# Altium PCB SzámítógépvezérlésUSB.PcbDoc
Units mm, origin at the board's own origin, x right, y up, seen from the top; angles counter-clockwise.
Board outline 152.4 x 101.6 mm, 2 copper layers (Top Layer, Bottom Layer); 19 components, 15 nets, 67 pads, 0 vias.
Unrouted connection lines stored in the file: 2.
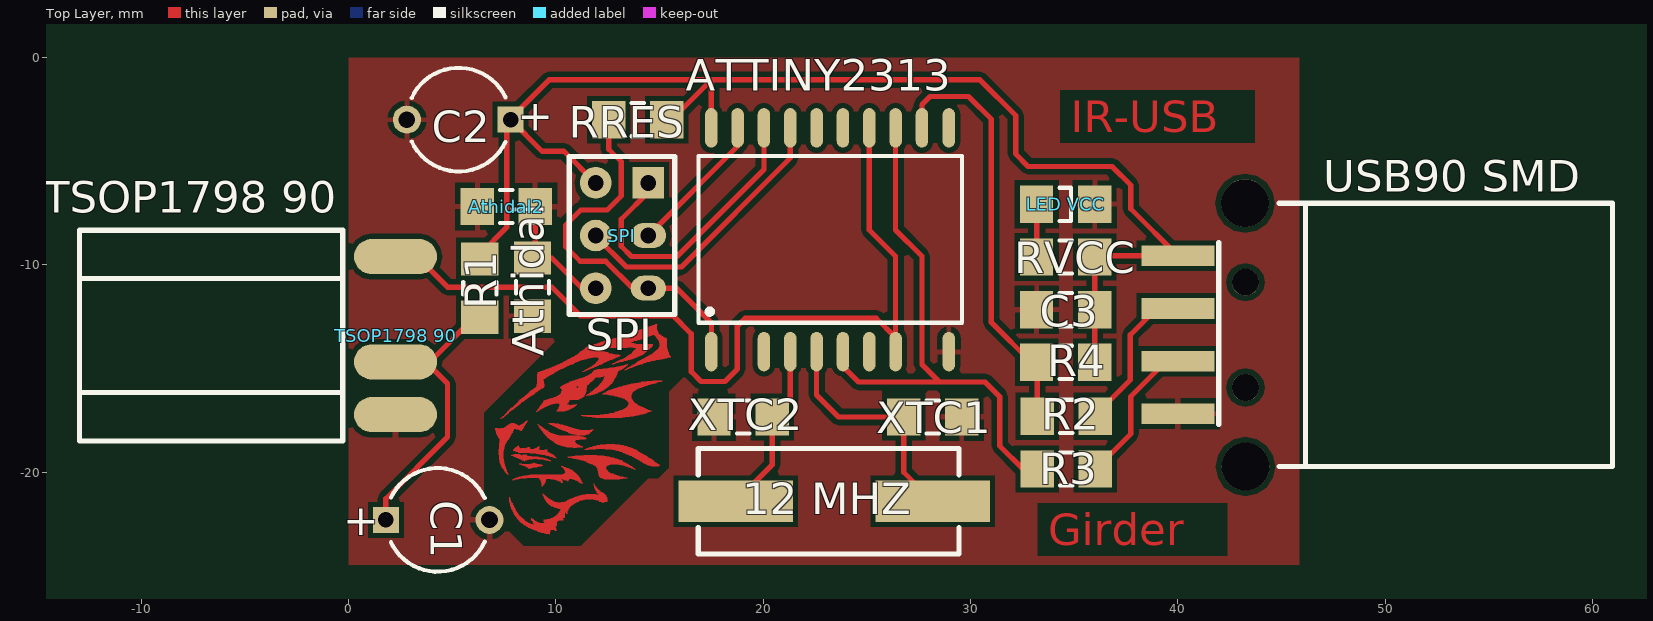
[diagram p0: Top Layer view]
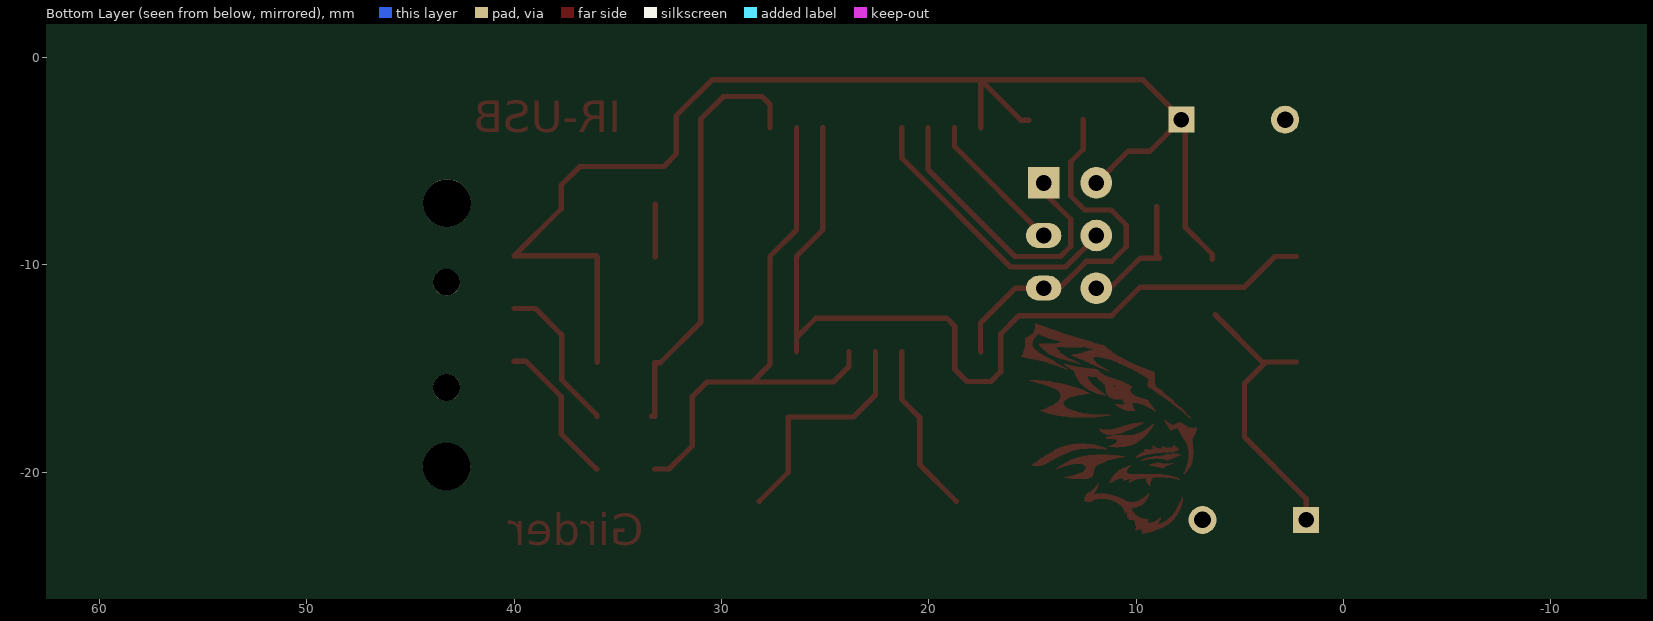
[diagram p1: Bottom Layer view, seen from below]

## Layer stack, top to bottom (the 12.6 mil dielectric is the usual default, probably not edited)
Top Layer: signal copper 0.0356
Dielectric: dielectric 0.32, FR-4, Dk 4.8
Bottom Layer: signal copper 0.036

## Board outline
-45.995,-61.098 106.405,-61.098 106.405,40.502 -45.995,40.502

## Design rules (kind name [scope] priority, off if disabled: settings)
Clearance [All] p1: gap=0.254
ComponentClearance [All] p1: gap=0.254 collisioncheckmode=3 verticalgap=0.254
PolygonConnect [All] p1: connectstyle=Relief reliefconductorwidth=0.254 reliefentries=4 polygonreliefangle="90 Angle"
RoutingVias [All] p1: holewidth=0.711 width=1.27 viastyle="Through Hole" minholewidth=0.711 minwidth=1.27 maxholewidth=0.711 maxwidth=1.27
SolderMaskExpansion [All] p1: expansion=0.102
TestPointUsage [All] p1: valid=0 allowmultiple=FALSE
Testpoint [All] p1: side=15 testpointundercomponent=TRUE minsize=1.016 maxsize=2.54 preferedsize=1.524 minholesize=0 maxholesize=1.016 preferedholesize=0.813 testpointgrid=0.025 style=1023 order=0123456789
Width [All] p1: maxlimit=0.254 minlimit=0.254 preferedwidth=0.254
18 further rules are at their usual default settings.

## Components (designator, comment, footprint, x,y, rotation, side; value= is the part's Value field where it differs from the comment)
"12 MHZ" "12 MHZ" Quartz 28.173,-21.401 r180 top (schematic designator "? MHZ")
Athidal "Res" "SM 3216[1206]" 8.869,-11.075 r90 top
Athidal2 "Res" "SM 3216[1206]" 7.602,-7.187 r180 top
ATTINY2313 "ATTINY2313" ATTINY2313 17.505,-14.172 r0 top
C1 "Cap Pol1" CAPPR5-5x5 4.297,-22.3 r0 top
C2 "Cap Pol1" CAPPR5-5x5 5.313,-2.996 r180 top
C3 "Cap" "SM 3216[1206]" 34.585,-12.158 r180 top
"LED VCC" "LED" "SM 3216[1206] - pol" 34.585,-7.078 r0 top
R1 "Res" "SM 3216[1206]" 6.329,-11.124 r90 top
R2 "Res" "SM 3216[1206]" 34.61,-17.303 r0 top
R3 "Res" "SM 3216[1206]" 34.61,-19.843 r0 top
R4 "Res" "SM 3216[1206]" 34.585,-14.698 r180 top
RRES "Res" "SM 3216[1206]" 13.949,-2.996 r180 top
RVCC "Res" "SM 3216[1206]" 34.585,-9.618 r180 top
SPI "SPI" SPI 11.917,-6.044 r0 top
"TSOP1798 90" "TSOP17xx90°" TSOP17xx90° 2.265,-17.22 r0 top (schematic designator TSOP17xx90°)
"USB90 SMD" "USB90° SMD" "USB90° SMD" 46.155,-7.025 r270 top (schematic designator "USB90° SMD")
XTC1 "Cap" "SM 3216[1206]" 28.173,-17.337 r0 top
XTC2 "Cap" "SM 3216[1206]" 19.029,-17.337 r180 top

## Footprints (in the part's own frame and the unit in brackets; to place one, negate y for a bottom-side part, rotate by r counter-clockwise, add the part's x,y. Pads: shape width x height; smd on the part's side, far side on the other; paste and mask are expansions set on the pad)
ATTINY2313 [mm]
  oval 0.6x1.9 smd: 1(-0.013,-0.013) 3(2.527,-0.013) 4(3.797,-0.013) 5(5.067,-0.013) 6(6.337,-0.013) 7(7.607,-0.013) 8(8.877,-0.013) 10(11.443,-0.013) 11(11.443,10.782) 12(10.147,10.782) 13(8.877,10.782) 14(7.607,10.782) 15(6.337,10.782) 16(5.067,10.782) 17(3.797,10.782) 18(2.527,10.782) 19(1.257,10.782) 20(-0.013,10.782)
  round 0 smd: 2(1.257,-0.013) 9(10.147,-0.013)
  silkscreen extent -0.62,1.38 12.08,9.42
CAPPR5-5x5 [mm] "Capacitor, Electrolytic, Radial; Body 5 x 5 mm (Dia.xH typ); Pin Spacing 5 mm (typ)"
  rect 1.25x1.25 hole 0.75: 1(-2.5,0)
  round 1.35 hole 0.8: 2(2.5,0)
  silkscreen extent -2.26,-2.5 2.27,2.5
Quartz [mm]
  rect 5.5x2 smd: 1(0,0) 2(9.5,0)
  silkscreen extent -1.27,-2.54 11.3,2.54
"SM 3216[1206]" [mm] "Chip Resistor; Body 3.2 x 1.6 mm (LxW typ)"
  rect 1.6x1.8 smd: 1(-1.4,0) 2(1.4,0)
  silkscreen extent -0.3,-0.8 0.3,0.8
"SM 3216[1206] - pol" [mm] "Polarized Chip; Body 3.2 x 1.6 mm (LxW typ)"
  rect 1.6x1.8 smd: 1(-1.4,0) 2(1.4,0)
  silkscreen extent -0.3,-0.8 0.25,0.8
SPI [mil]
  round 60 hole 30: 1(0,0) 3(0,-100) 5(0,-200)
  rect 60x60 hole 30: 2(100,0)
  oval 66.93x47.24 hole 30: 4(100,-100) 6(100,-200)
  silkscreen extent -50,-250 150,50
TSOP17xx90° [mm]
  oval 4x1.7 smd: 1(0,0) 2(0,2.54) 3(0,7.62)
  silkscreen extent -15.24,-1.27 -2.54,8.89
"USB90° SMD" [mm]
  round 2.3 hole 2.3: 0(0,-2.921) 0(12.7,-2.9)
  round 1.3 hole 1.3: 0(3.81,-2.9) 0(8.89,-2.9)
  rect 1x3.5 smd: 1(2.54,-6.155) 2(5.08,-6.155) 3(7.62,-6.155) 4(10.16,-6.155)
  silkscreen extent 0,-4.19 12.7,14.8

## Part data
"12 MHZ": library part Quartz, "SMD"
Athidal Athidal2 R1 R2 R3 R4 RRES RVCC: "Resistor"
C1 C2: "Polarized Capacitor (Radial)"
C3 XTC1 XTC2: "Capacitor"

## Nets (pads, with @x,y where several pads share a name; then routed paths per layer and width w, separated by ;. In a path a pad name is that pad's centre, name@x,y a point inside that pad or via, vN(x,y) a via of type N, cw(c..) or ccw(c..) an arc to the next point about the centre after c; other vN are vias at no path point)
GND: "LED VCC.2" "TSOP1798 90.1" "USB90 SMD.4" Athidal2.1 Athidal2.2 Athidal.1 Athidal.2 ATTINY2313.10 C1.2 C2.2 C3.2 SPI.5 XTC1.2 XTC2.2 | length 6.2
  Top Layer w0.254: Athidal.2 9.8,-9.675 11.249,-11.124 SPI.5 ; Athidal.2 9.002,-9.542 Athidal2.1
MISO: ATTINY2313.18 SPI.2 | length 14.4
  Top Layer w0.254: SPI.2 14.457,-6.493 13.15,-7.8 13.15,-9.1 13.642,-9.592 15.833,-9.592 20.032,-5.393 ATTINY2313.18
MOSI: ATTINY2313.17 SPI.3 | length 13.7
  Top Layer w0.254: SPI.3 11.917,-8.617 13.4,-10.1 16.05,-10.1 21.302,-4.848 ATTINY2313.17
NetC1_1: "TSOP1798 90.2" C1.1 R1.1 | length 14
  Top Layer w0.254: C1.1 1.797,-21.278 4.775,-18.3 4.775,-15.725 3.73,-14.68 2.265,-14.68 ; 3.913,-14.68 R1.1@6.199,-12.394
"NetLED VCC_1": "LED VCC.1" RVCC.2 | length 2.5
  Top Layer w0.254: RVCC.2 33.185,-7.078
NetR2_2: "USB90 SMD.2" R2.2 | length 7.5
  Top Layer w0.254: R2.2 36.01,-17.24 37.7,-15.55 37.7,-13.375 38.97,-12.105 40,-12.105
NetR3_2: "USB90 SMD.3" R3.2 | length 7.2
  Top Layer w0.254: R3.2 36.032,-19.843 37.725,-18.15 37.725,-16.35 39.43,-14.645 40,-14.645
PB0: ATTINY2313.12 R2.1 R4.2 | length 20.6
  Top Layer w0.254: ATTINY2313.12 27.652,-2.273 28.05,-1.875 29.9,-1.875 31,-2.975 31,-12.775 32.948,-14.723 33.21,-14.723 R2.1 R2.1@33.372,-17.303
PB1: ATTINY2313.6 ATTINY2313.13 R3.1 | length 26.7
  Top Layer w0.254: ATTINY2313.6 23.842,-14.892 24.6,-15.65 30.7,-15.65 31.4,-16.35 31.4,-18.725 32.518,-19.843 R3.1 ; ATTINY2313.13 26.382,-8.312 27.652,-9.582 27.652,-14.802 28.5,-15.65
PB2: "TSOP1798 90.3" ATTINY2313.8 ATTINY2313.14 | length 41.9
  Top Layer w0.254: 2.265,-9.6 3.3,-9.6 4.775,-11.075 9.8,-11.075 11.175,-12.45 15.65,-12.45 16.525,-13.325 16.525,-15.15 17,-15.625 18.15,-15.625 18.75,-15.025 18.75,-12.95 19.125,-12.575 25.45,-12.575 ATTINY2313.8@26.382,-13.507 ; ATTINY2313.14 25.112,-8.312 26.382,-9.582 ATTINY2313.8
RES: ATTINY2313.1 RRES.2 SPI.6 | length 18.2
  Top Layer w0.254: RRES.2 12.549,-4.424 13.15,-5.025 13.15,-6.675 12.475,-7.35 11.2,-7.35 10.475,-8.075 10.475,-9.125 11.175,-9.825 12.4,-9.825 13.699,-11.124 15.824,-11.124 17.5,-12.8 17.5,-14.177 ATTINY2313.1
SCK: ATTINY2313.19 SPI.4 | length 7
  Top Layer w0.254: SPI.4 18.762,-4.279 ATTINY2313.19
VCC: "USB90 SMD.1" ATTINY2313.20 C2.1 C3.1 R1.2 R4.1 RRES.1 RVCC.1 SPI.1 | length 65.5
  Top Layer w0.254: R1.2 6.329,-9.487 7.625,-8.191 7.625,-3.184 C2.1 9.337,-4.52 10.393,-4.52 SPI.1 ; C2.1@7.783,-2.966 9.675,-1.075 30.45,-1.075 32.175,-2.8 32.175,-4.65 32.775,-5.25 36.825,-5.25 37.725,-6.15 37.725,-7.29 40,-9.565 36.038,-9.565 RVCC.1 R4.1 ; RRES.1@15.174,-3.021 15.564,-3.021 17.492,-1.093 ATTINY2313.20
XT1: "12 MHZ.1" ATTINY2313.5 XTC1.1 | length 11.4
  Top Layer w0.254: ATTINY2313.5 22.572,-16.272 23.637,-17.337 XTC1.1 26.773,-20.001 28.173,-21.401
XT2: "12 MHZ.2" ATTINY2313.4 XTC2.1 | length 8.3
  Top Layer w0.254: 18.673,-21.401 20.429,-19.645 XTC2.1 20.463,-17.337 21.302,-16.498 ATTINY2313.4
pads on no net: "USB90 SMD.0" ATTINY2313.2 ATTINY2313.3 ATTINY2313.7 ATTINY2313.9 ATTINY2313.11 ATTINY2313.15 ATTINY2313.16
copper on no net: | length 678.6
  Top Layer w0.025: 7.068,-17.933 7.957,-17.933 ; 7.068,-17.908 7.957,-17.908 ; 7.068,-17.882 7.221,-17.882 ; 7.094,-18.009 7.906,-18.009 ; 7.094,-17.984 7.932,-17.984 ; 7.094,-17.959 7.957,-17.959 ; 7.119,-18.111 7.856,-18.111 ; 7.119,-18.086 7.881,-18.086 ; 7.119,-18.06 7.906,-18.06 ; 7.119,-18.035 7.906,-18.035 ; 7.144,-18.136 7.856,-18.136 ; 7.17,-18.213 7.805,-18.213 ; 7.17,-18.187 7.83,-18.187 ; 7.17,-18.162 7.856,-18.162 ; 7.195,-18.238 7.805,-18.238 ; 7.221,-18.314 7.754,-18.314 ; 7.221,-18.289 7.779,-18.289 ; 7.221,-18.263 7.805,-18.263 ; 7.246,-19.127 7.449,-19.127 ; 7.246,-19.102 7.449,-19.102 ; 7.246,-19.076 7.449,-19.076 ; 7.246,-19.051 7.449,-19.051 ; 7.246,-19.025 7.449,-19.025 ; 7.246,-19 7.449,-19 ; 7.246,-18.975 7.449,-18.975 ; 7.246,-18.949 7.449,-18.949 ; 7.246,-18.924 7.475,-18.924 ; 7.246,-18.898 7.475,-18.898 ; 7.271,-19.381 7.475,-19.381 ; 7.271,-19.356 7.449,-19.356 ; 7.271,-19.33 7.449,-19.33 ; 7.271,-19.305 7.449,-19.305 ; 7.271,-19.279 7.449,-19.279 ; 7.271,-19.254 7.449,-19.254 ; 7.271,-19.229 7.449,-19.229 ; 7.271,-19.203 7.449,-19.203 ; 7.271,-19.178 7.449,-19.178 ; 7.271,-19.152 7.449,-19.152 ; 7.271,-18.873 7.475,-18.873 ; 7.271,-18.848 7.5,-18.848 ; 7.271,-18.822 7.5,-18.822 ; 7.271,-18.797 7.5,-18.797 ; 7.271,-18.771 7.5,-18.771 ; 7.271,-18.746 7.5,-18.746 ; 7.271,-18.721 7.525,-18.721 ; 7.271,-18.695 7.525,-18.695 ; 7.271,-18.67 7.525,-18.67 ; 7.271,-18.644 7.525,-18.644 ; 7.271,-18.619 7.551,-18.619 ; 7.271,-18.594 7.576,-18.594 ; 7.271,-18.365 7.729,-18.365 ; 7.271,-18.34 7.754,-18.34 ; 7.297,-19.508 7.5,-19.508 ; 7.297,-19.483 7.5,-19.483 ; 7.297,-19.457 7.475,-19.457 ; 7.297,-19.432 7.475,-19.432 ; 7.297,-19.406 7.475,-19.406 ; 7.297,-18.568 7.576,-18.568 ; 7.297,-18.543 7.602,-18.543 ; 7.297,-18.517 7.627,-18.517 ; 7.297,-18.492 7.627,-18.492 ; 7.297,-18.467 7.652,-18.467 ; 7.297,-18.441 7.678,-18.441 ; 7.297,-18.416 7.703,-18.416 ; 7.297,-18.39 7.729,-18.39 ; 7.322,-19.559 7.5,-19.559 ; 7.322,-19.533 7.5,-19.533 ; 7.348,-19.635 7.525,-19.635 ; 7.348,-19.61 7.525,-19.61 ; 7.348,-19.584 7.5,-19.584 ; 7.348,-17.882 8.414,-17.882 ; 7.348,-17.4 7.373,-17.4 ; 7.373,-19.686 7.525,-19.686 ; 7.373,-19.66 7.525,-19.66 ; 7.373,-17.374 7.398,-17.374 ; 7.398,-19.737 7.551,-19.737 ; 7.398,-19.711 7.551,-19.711 ; 7.424,-19.787 7.576,-19.787 ; 7.424,-19.762 7.576,-19.762 ; 7.424,-17.349 7.449,-17.349 ; 7.424,-17.324 7.475,-17.324 ; 7.449,-19.813 7.576,-19.813 ; 7.449,-17.298 7.5,-17.298 ; 7.475,-19.864 7.602,-19.864 ; 7.475,-19.838 7.576,-19.838 ; 7.5,-19.914 7.627,-19.914 ; 7.5,-19.889 7.627,-19.889 ; 7.5,-17.857 8.414,-17.857 ; 7.5,-17.273 7.525,-17.273 ; 7.5,-17.247 7.551,-17.247 ; 7.525,-19.94 7.627,-19.94 ; 7.525,-17.832 8.414,-17.832 ; 7.525,-17.222 7.576,-17.222 ; 7.551,-19.965 7.627,-19.965 ; 7.551,-17.197 7.627,-17.197 ; 7.576,-19.991 7.652,-19.991 ; 7.576,-17.806 8.44,-17.806 ; 7.576,-17.171 7.652,-17.171 ; 7.602,-20.016 7.678,-20.016 ; 7.602,-17.781 8.44,-17.781 ; 7.602,-17.146 7.678,-17.146 ; 7.627,-20.041 7.678,-20.041 ; 7.627,-17.755 8.465,-17.755 ; 7.627,-17.12 7.729,-17.12 ; 7.652,-17.095 7.729,-17.095 ; 7.678,-20.092 7.703,-20.092 ; 7.678,-20.067 7.703,-20.067 ; 7.678,-17.73 8.186,-17.73 ; 7.678,-17.07 7.779,-17.07 ; 7.703,-17.705 8.135,-17.705 ; 7.729,-17.044 7.805,-17.044 ; 7.729,-17.019 7.83,-17.019 ; 7.754,-21.388 7.83,-21.388 ; 7.754,-21.362 7.83,-21.362 ; 7.754,-21.337 7.805,-21.337 ; 7.754,-21.311 7.805,-21.311 ; 7.754,-21.286 7.805,-21.286 ; 7.754,-21.261 7.805,-21.261 ; 7.754,-21.235 7.779,-21.235 ; 7.754,-21.21 7.779,-21.21 ; 7.754,-17.679 8.084,-17.679 ; 7.754,-16.993 7.881,-16.993 ; 7.779,-21.464 7.881,-21.464 ; 7.779,-21.438 7.856,-21.438 ; 7.779,-21.413 7.856,-21.413 ; 7.779,-17.654 8.033,-17.654 ; 7.779,-16.968 7.906,-16.968 ; 7.805,-21.616 7.957,-21.616 ; 7.805,-21.591 7.932,-21.591 ; 7.805,-21.565 7.906,-21.565 ; 7.805,-21.54 7.906,-21.54 ; 7.805,-21.515 7.906,-21.515 ; 7.805,-21.489 7.906,-21.489 ; 7.805,-16.943 7.957,-16.943 ; 7.83,-21.642 7.957,-21.642 ; 7.83,-16.917 7.957,-16.917 ; 7.856,-21.743 8.008,-21.743 ; 7.856,-21.718 7.983,-21.718 ; 7.856,-21.692 7.983,-21.692 ; 7.856,-21.667 7.983,-21.667 ; 7.856,-19.178 8.313,-19.178 ; 7.856,-17.628 7.983,-17.628 ; 7.856,-16.892 8.008,-16.892 ; 7.881,-21.794 8.033,-21.794 ; 7.881,-21.769 8.033,-21.769 ; 7.906,-21.87 8.084,-21.87 ; 7.906,-21.845 8.059,-21.845 ; 7.906,-21.819 8.059,-21.819 ; 7.906,-20.372 7.957,-20.372 ; 7.906,-20.346 8.008,-20.346 ; 7.906,-19.152 8.313,-19.152 ; 7.906,-16.866 8.033,-16.866 ; 7.932,-21.896 8.11,-21.896 ; 7.932,-19.203 8.618,-19.203 ; 7.932,-18.949 9.583,-18.949 ; 7.932,-18.924 9.227,-18.924 ; 7.932,-16.841 8.059,-16.841 ; 7.957,-21.972 8.16,-21.972 ; 7.957,-21.946 8.135,-21.946 ; 7.957,-21.921 8.135,-21.921 ; 7.957,-18.898 8.77,-18.898 ; 7.957,-16.816 8.11,-16.816 ; 7.983,-22.023 8.186,-22.023 ; 7.983,-21.997 8.186,-21.997 ; 7.983,-20.321 8.186,-20.321 ; 7.983,-19.229 8.821,-19.229 ; 7.983,-19.127 8.262,-19.127 ; 7.983,-18.873 8.77,-18.873 ; 7.983,-16.79 8.135,-16.79 ; 8.008,-22.048 8.211,-22.048 ; 8.008,-20.295 8.262,-20.295 ; 8.008,-18.848 8.262,-18.848 ; 8.008,-16.765 8.186,-16.765 ; 8.033,-22.099 8.262,-22.099 ; 8.033,-22.073 8.211,-22.073 ; 8.033,-18.975 9.583,-18.975 ; 8.033,-18.822 8.262,-18.822 ; 8.033,-16.739 8.186,-16.739 ; 8.059,-19.254 9.151,-19.254 ; 8.059,-16.714 8.237,-16.714 ; 8.084,-22.15 8.313,-22.15 ; 8.084,-22.124 8.287,-22.124 ; 8.084,-20.27 8.567,-20.27 ; 8.084,-19.279 9.227,-19.279 ; 8.084,-19 9.583,-19 ; 8.084,-18.797 8.237,-18.797 ; 8.084,-17.908 8.389,-17.908 ; 8.084,-16.689 8.262,-16.689 ; 8.11,-22.175 8.338,-22.175 ; 8.11,-18.771 8.211,-18.771 ; 8.135,-22.226 8.389,-22.226 ; 8.135,-22.2 8.364,-22.2 ; 8.135,-18.746 8.211,-18.746 ; 8.135,-16.663 8.313,-16.663 ; 8.135,-16.638 8.313,-16.638 ; 8.16,-22.251 8.414,-22.251 ; 8.186,-22.277 8.44,-22.277 ; 8.186,-20.245 11.132,-20.245 ; 8.186,-19.305 9.38,-19.305 ; 8.186,-19.025 9.634,-19.025 ; 8.186,-18.721 8.211,-18.721 ; 8.186,-16.612 8.364,-16.612 ; 8.211,-22.302 8.465,-22.302 ; 8.211,-19.33 9.456,-19.33 ; 8.211,-17.933 8.364,-17.933 ; 8.211,-16.587 8.414,-16.587 ; 8.211,-16.562 8.44,-16.562 ; 8.237,-22.327 8.491,-22.327 ; 8.237,-20.219 11.107,-20.219 ; 8.237,-19.584 8.364,-19.584 ; 8.262,-22.353 8.541,-22.353 ; 8.262,-17.959 8.364,-17.959 ; 8.262,-16.536 8.465,-16.536 ; 8.262,-16.511 8.491,-16.511 ; 8.287,-22.378 8.592,-22.378 ; 8.287,-19.356 8.872,-19.356 ; 8.287,-17.73 8.491,-17.73 ; 8.313,-19.61 9.227,-19.61 ; 8.313,-18.848 8.491,-18.848 ; 8.313,-17.984 8.364,-17.984 ; 8.313,-17.705 8.491,-17.705 ; 8.313,-16.485 8.541,-16.485 ; 8.338,-22.404 8.643,-22.404 ; 8.338,-16.46 8.567,-16.46 ; 8.364,-22.429 8.668,-22.429 ; 8.364,-20.194 11.107,-20.194 ; 8.364,-19.635 9.329,-19.635 ; 8.364,-19.406 8.592,-19.406 ; 8.364,-19.381 8.668,-19.381 ; 8.364,-19.178 8.592,-19.178 ; 8.364,-17.679 8.516,-17.679 ; 8.364,-16.435 8.618,-16.435 ; 8.389,-22.454 8.745,-22.454 ; 8.389,-17.654 8.541,-17.654 ; 8.389,-16.409 8.643,-16.409 ; 8.414,-22.48 8.795,-22.48 ; 8.414,-19.152 8.592,-19.152 ; 8.414,-16.384 8.668,-16.384 ; 8.44,-22.505 8.872,-22.505 ; 8.44,-20.168 11.081,-20.168 ; 8.44,-19.66 9.354,-19.66 ; 8.44,-19.432 8.491,-19.432 ; 8.44,-17.628 8.541,-17.628 ; 8.44,-17.603 8.567,-17.603 ; 8.465,-22.531 8.948,-22.531 ; 8.465,-19.457 8.491,-19.457 ; 8.465,-16.358 8.719,-16.358 ; 8.491,-19.686 9.303,-19.686 ; 8.491,-17.578 8.592,-17.578 ; 8.491,-16.333 8.745,-16.333 ; 8.516,-17.552 8.592,-17.552 ; 8.516,-16.308 8.795,-16.308 ; 8.541,-22.556 10.015,-22.556 ; 8.541,-18.848 8.745,-18.848 ; 8.541,-16.282 8.821,-16.282 ; 8.567,-19.711 9.151,-19.711 ; 8.592,-22.607 9.964,-22.607 ; 8.592,-22.581 9.938,-22.581 ; 8.592,-19.737 9.075,-19.737 ; 8.592,-18.822 8.745,-18.822 ; 8.592,-17.527 8.643,-17.527 ; 8.592,-16.257 8.872,-16.257 ; 8.592,-16.231 8.897,-16.231 ; 8.643,-20.143 11.056,-20.143 ; 8.643,-19.762 8.897,-19.762 ; 8.643,-18.797 8.745,-18.797 ; 8.643,-16.206 8.948,-16.206 ; 8.668,-22.658 9.964,-22.658 ; 8.668,-22.632 9.964,-22.632 ; 8.668,-19.787 8.821,-19.787 ; 8.668,-16.181 8.948,-16.181 ; 8.694,-16.155 8.999,-16.155 ; 8.719,-19.813 8.745,-19.813 ; 8.719,-16.13 9.049,-16.13 ; 8.77,-22.683 9.989,-22.683 ; 8.77,-20.118 11.031,-20.118 ; 8.77,-19.051 9.684,-19.051 ; 8.77,-16.104 9.1,-16.104 ; 8.795,-22.708 9.989,-22.708 ; 8.795,-19.584 9.075,-19.584 ; 8.795,-18.898 9.176,-18.898 ; 8.795,-16.079 9.126,-16.079 ; 8.821,-22.302 8.922,-22.302 ; 8.821,-22.277 8.897,-22.277 ; 8.821,-22.251 8.872,-22.251 ; 8.821,-22.226 8.846,-22.226 ; 8.821,-16.054 9.151,-16.054 ; 8.846,-22.327 8.973,-22.327 ; 8.872,-22.734 10.015,-22.734 ; 8.872,-22.378 9.075,-22.378 ; 8.872,-22.353 9.049,-22.353 ; 8.872,-16.028 9.202,-16.028 ; 8.872,-16.003 9.227,-16.003 ; 8.897,-22.759 10.015,-22.759 ; 8.897,-22.429 9.202,-22.429 ; 8.897,-22.404 9.151,-22.404 ; 8.897,-19.559 8.999,-19.559 ; 8.922,-22.454 10.04,-22.454 ; 8.922,-19.533 8.948,-19.533 ; 8.922,-15.977 9.278,-15.977 ; 8.948,-22.48 10.04,-22.48 ; 8.948,-18.873 9.176,-18.873 ; 8.948,-15.952 9.303,-15.952 ; 8.973,-22.785 9.735,-22.785 ; 8.973,-22.505 10.04,-22.505 ; 8.999,-22.531 10.04,-22.531 ; 8.999,-18.848 9.176,-18.848 ; 8.999,-15.927 9.354,-15.927 ; 9.024,-15.901 9.405,-15.901 ; 9.049,-19.076 9.735,-19.076 ; 9.049,-17.07 9.1,-17.07 ; 9.049,-15.876 9.405,-15.876 ; 9.075,-22.81 9.735,-22.81 ; 9.075,-18.822 9.202,-18.822 ; 9.075,-15.85 9.43,-15.85 ; 9.075,-15.825 9.43,-15.825 ; 9.075,-15.8 9.43,-15.8 ; 9.075,-15.774 9.43,-15.774 ; 9.075,-15.749 9.43,-15.749 ; 9.1,-18.797 9.202,-18.797 ; 9.1,-17.044 9.126,-17.044 ; 9.1,-17.019 9.151,-17.019 ; 9.1,-15.723 9.43,-15.723 ; 9.1,-15.698 9.405,-15.698 ; 9.1,-15.673 9.405,-15.673 ; 9.1,-15.647 9.405,-15.647 ; 9.1,-15.622 9.405,-15.622 ; 9.1,-15.596 9.38,-15.596 ; 9.1,-15.571 9.38,-15.571 ; 9.1,-15.546 9.38,-15.546 ; 9.1,-15.52 9.38,-15.52 ; 9.1,-15.495 9.405,-15.495 ; 9.1,-15.469 9.456,-15.469 ; 9.1,-15.444 9.507,-15.444 ; 9.1,-15.419 9.507,-15.419 ; 9.1,-15.393 9.583,-15.393 ; 9.1,-15.368 9.583,-15.368 ; 9.1,-15.342 9.659,-15.342 ; 9.1,-15.317 9.684,-15.317 ; 9.1,-15.292 9.735,-15.292 ; 9.1,-15.266 9.786,-15.266 ; 9.126,-22.835 9.735,-22.835 ; 9.126,-19.356 9.557,-19.356 ; 9.126,-17.679 9.151,-17.679 ; 9.126,-16.993 9.227,-16.993 ; 9.126,-16.968 9.227,-16.968 ; 9.126,-15.241 9.811,-15.241 ; 9.126,-15.215 9.888,-15.215 ; 9.126,-15.19 9.913,-15.19 ; 9.151,-18.771 9.202,-18.771 ; 9.151,-17.705 9.176,-17.705 ; 9.176,-20.27 11.158,-20.27 ; 9.176,-19.102 9.786,-19.102 ; 9.176,-18.746 9.202,-18.746 ; 9.176,-17.755 9.253,-17.755 ; 9.176,-17.73 9.202,-17.73 ; 9.176,-16.943 9.303,-16.943 ; 9.176,-16.917 9.329,-16.917 ; 9.202,-17.806 9.329,-17.806 ; 9.202,-17.781 9.278,-17.781 ; 9.202,-16.892 9.38,-16.892 ; 9.202,-16.866 9.405,-16.866 ; 9.227,-22.861 9.71,-22.861 ; 9.227,-20.321 9.532,-20.321 ; 9.227,-20.295 11.183,-20.295 ; 9.227,-17.857 9.354,-17.857 ; 9.227,-17.832 9.354,-17.832 ; 9.227,-16.841 9.456,-16.841 ; 9.227,-15.165 9.964,-15.165 ; 9.253,-20.346 9.507,-20.346 ; 9.253,-16.816 9.532,-16.816 ; 9.278,-20.422 9.507,-20.422 ; 9.278,-20.397 9.507,-20.397 ; 9.278,-20.372 9.507,-20.372 ; 9.278,-17.908 9.43,-17.908 ; 9.278,-17.882 9.405,-17.882 ; 9.278,-16.79 9.557,-16.79 ; 9.278,-16.765 9.634,-16.765 ; 9.278,-15.139 10.015,-15.139 ; 9.303,-22.886 9.71,-22.886 ; 9.303,-20.473 9.481,-20.473 ; 9.303,-20.448 9.481,-20.448 ; 9.303,-17.959 9.507,-17.959 ; 9.303,-17.933 9.481,-17.933 ; 9.303,-16.739 9.684,-16.739 ; 9.329,-20.651 9.354,-20.651 ; 9.329,-20.626 9.354,-20.626 ; 9.329,-20.6 9.38,-20.6 ; 9.329,-20.575 9.405,-20.575 ; 9.329,-20.549 9.43,-20.549 ; 9.329,-20.524 9.43,-20.524 ; 9.329,-20.499 9.456,-20.499 ; 9.329,-19.127 9.811,-19.127 ; 9.329,-17.984 9.557,-17.984 ; 9.329,-16.714 9.761,-16.714 ; 9.329,-16.689 9.811,-16.689 ; 9.354,-21.083 9.43,-21.083 ; 9.354,-21.057 9.38,-21.057 ; 9.354,-21.032 9.38,-21.032 ; 9.354,-18.035 9.634,-18.035 ; 9.354,-18.009 9.634,-18.009 ; 9.354,-16.663 9.938,-16.663 ; 9.354,-16.638 10.599,-16.638 ; 9.354,-15.114 10.065,-15.114 ; 9.38,-21.108 9.456,-21.108 ; 9.38,-18.06 9.71,-18.06 ; 9.38,-16.612 10.599,-16.612 ; 9.405,-22.353 10.065,-22.353 ; 9.405,-22.327 10.142,-22.327 ; 9.405,-22.302 10.345,-22.302 ; 9.405,-21.184 9.557,-21.184 ; 9.405,-21.159 9.507,-21.159 ; 9.405,-21.134 9.481,-21.134 ; 9.405,-19.381 9.634,-19.381 ; 9.405,-18.086 9.735,-18.086 ; 9.405,-16.587 10.624,-16.587 ; 9.405,-16.562 10.65,-16.562 ; 9.405,-15.088 10.091,-15.088 ; 9.43,-22.912 9.71,-22.912 ; 9.43,-22.378 10.04,-22.378 ; 9.43,-21.235 9.608,-21.235 ; 9.43,-21.21 9.583,-21.21 ; 9.43,-18.111 9.811,-18.111 ; 9.456,-22.429 10.04,-22.429 ; 9.456,-22.404 10.04,-22.404 ; 9.456,-21.286 9.684,-21.286 ; 9.456,-21.261 9.634,-21.261 ; 9.456,-18.924 9.583,-18.924 ; 9.456,-18.136 9.862,-18.136 ; 9.456,-16.536 10.65,-16.536 ; 9.481,-21.311 9.735,-21.311 ; 9.481,-19.406 9.659,-19.406 ; 9.481,-19.152 9.862,-19.152 ; 9.481,-18.162 9.964,-18.162 ; 9.481,-15.063 10.142,-15.063 ; 9.507,-22.937 9.71,-22.937 ; 9.507,-21.362 9.811,-21.362 ; 9.507,-21.337 9.761,-21.337 ; 9.507,-18.213 10.142,-18.213 ; 9.507,-18.187 10.015,-18.187 ; 9.532,-21.388 9.862,-21.388 ; 9.532,-16.511 10.65,-16.511 ; 9.532,-15.038 10.192,-15.038 ; 9.557,-21.413 9.938,-21.413 ; 9.557,-19.178 9.888,-19.178 ; 9.557,-18.263 11.183,-18.263 ; 9.557,-18.238 11.107,-18.238 ; 9.583,-22.277 10.345,-22.277 ; 9.583,-21.438 10.065,-21.438 ; 9.583,-18.289 11.31,-18.289 ; 9.608,-21.464 10.929,-21.464 ; 9.608,-18.314 11.361,-18.314 ; 9.608,-15.012 10.243,-15.012 ; 9.634,-21.489 10.878,-21.489 ; 9.634,-19.432 9.735,-19.432 ; 9.634,-16.485 11.081,-16.485 ; 9.659,-21.515 10.853,-21.515 ; 9.659,-18.34 11.437,-18.34 ; 9.659,-17.628 9.913,-17.628 ; 9.684,-22.962 9.71,-22.962 ; 9.684,-21.54 10.802,-21.54 ; 9.684,-19.203 9.913,-19.203 ; 9.684,-18.365 11.462,-18.365 ; 9.684,-16.46 11.132,-16.46 ; 9.684,-14.987 10.319,-14.987 ; 9.71,-19.457 9.761,-19.457 ; 9.71,-18.39 11.412,-18.39 ; 9.71,-17.654 10.142,-17.654 ; 9.735,-22.251 10.319,-22.251 ; 9.735,-21.565 10.777,-21.565 ; 9.735,-19.229 9.938,-19.229 ; 9.735,-18.416 11.132,-18.416 ; 9.735,-17.679 10.192,-17.679 ; 9.735,-14.961 10.345,-14.961 ; 9.761,-22.226 10.294,-22.226 ; 9.761,-21.591 10.751,-21.591 ; 9.761,-20.321 10.65,-20.321 ; 9.786,-21.616 10.726,-21.616 ; 9.786,-18.441 10.954,-18.441 ; 9.786,-16.435 11.183,-16.435 ; 9.811,-18.467 10.929,-18.467 ; 9.811,-17.705 10.319,-17.705 ; 9.811,-14.936 10.421,-14.936 ; 9.837,-22.2 10.319,-22.2 ; 9.837,-19.254 9.964,-19.254 ; 9.837,-18.492 10.904,-18.492 ; 9.837,-17.73 10.37,-17.73 ; 9.837,-14.911 10.446,-14.911 ; 9.862,-22.175 10.421,-22.175 ; 9.862,-21.642 10.7,-21.642 ; 9.862,-16.409 11.234,-16.409 ; 9.888,-19.279 9.989,-19.279 ; 9.888,-18.517 10.904,-18.517 ; 9.888,-17.755 10.497,-17.755 ; 9.913,-22.785 10.015,-22.785 ; 9.913,-22.15 10.421,-22.15 ; 9.913,-21.667 10.675,-21.667 ; 9.913,-18.543 10.929,-18.543 ; 9.913,-16.384 11.259,-16.384 ; 9.913,-14.885 10.497,-14.885 ; 9.938,-20.346 10.269,-20.346 ; 9.964,-22.81 10.015,-22.81 ; 9.964,-22.124 10.421,-22.124 ; 9.964,-21.692 10.65,-21.692 ; 9.964,-18.568 10.954,-18.568 ; 9.964,-17.781 10.573,-17.781 ; 9.964,-14.86 10.548,-14.86 ; 9.989,-22.581 10.015,-22.581 ; 9.989,-22.099 10.421,-22.099 ; 9.989,-19.305 10.015,-19.305 ; 9.989,-17.806 10.624,-17.806 ; 10.015,-20.372 10.269,-20.372 ; 10.015,-18.594 10.954,-18.594 ; 10.015,-16.358 11.285,-16.358 ; 10.04,-22.073 10.421,-22.073 ; 10.04,-22.048 10.421,-22.048 ; 10.04,-17.832 10.726,-17.832 ; 10.04,-17.044 10.421,-17.044 ; 10.04,-16.333 11.335,-16.333 ; 10.04,-14.834 10.624,-14.834 ; 10.065,-21.718 10.65,-21.718 ; 10.065,-18.619 11.005,-18.619 ; 10.065,-17.019 10.497,-17.019 ; 10.065,-14.809 10.65,-14.809 ; 10.091,-22.023 10.421,-22.023 ; 10.091,-21.997 10.421,-21.997 ; 10.091,-20.397 10.294,-20.397 ; 10.091,-18.644 11.031,-18.644 ; 10.091,-17.857 10.777,-17.857 ; 10.091,-16.993 10.599,-16.993 ; 10.091,-16.968 10.624,-16.968 ; 10.091,-16.308 11.361,-16.308 ; 10.116,-21.972 10.421,-21.972 ; 10.116,-16.943 10.7,-16.943 ; 10.116,-16.282 11.361,-16.282 ; 10.142,-21.946 10.421,-21.946 ; 10.142,-21.743 10.624,-21.743 ; 10.142,-20.422 10.294,-20.422 ; 10.142,-17.882 10.878,-17.882 ; 10.142,-16.917 10.726,-16.917 ; 10.142,-16.892 10.777,-16.892 ; 10.142,-16.866 10.827,-16.866 ; 10.142,-14.784 10.726,-14.784 ; 10.167,-21.921 10.421,-21.921 ; 10.167,-21.896 10.548,-21.896 ; 10.167,-16.841 10.853,-16.841 ; 10.167,-16.816 10.904,-16.816 ; 10.167,-16.689 10.523,-16.689 ; 10.167,-16.663 10.548,-16.663 ; 10.192,-21.87 10.548,-21.87 ; 10.192,-18.67 11.107,-18.67 ; 10.192,-17.908 10.929,-17.908 ; 10.192,-16.79 10.929,-16.79 ; 10.192,-16.765 10.954,-16.765 ; 10.192,-16.739 10.624,-16.739 ; 10.192,-16.714 10.497,-16.714 ; 10.192,-16.257 11.386,-16.257 ; 10.192,-16.231 11.386,-16.231 ; 10.218,-21.845 10.573,-21.845 ; 10.218,-15.901 10.98,-15.901 ; 10.218,-14.758 10.827,-14.758 ; 10.243,-21.819 10.599,-21.819 ; 10.243,-21.794 10.599,-21.794 ; 10.243,-21.769 10.599,-21.769 ; 10.243,-20.448 10.319,-20.448 ; 10.243,-16.206 11.412,-16.206 ; 10.243,-16.181 11.412,-16.181 ; 10.243,-15.927 11.005,-15.927 ; 10.243,-15.876 10.98,-15.876 ; 10.243,-14.733 10.853,-14.733 ; 10.269,-21.438 10.954,-21.438 ; 10.269,-20.473 10.319,-20.473 ; 10.269,-19.711 10.319,-19.711 ; 10.269,-18.695 11.158,-18.695 ; 10.269,-17.933 11.056,-17.933 ; 10.269,-16.155 11.437,-16.155 ; 10.269,-16.13 11.437,-16.13 ; 10.269,-16.104 11.462,-16.104 ; 10.269,-15.977 11.462,-15.977 ; 10.269,-15.952 11.462,-15.952 ; 10.269,-15.85 10.98,-15.85 ; 10.294,-19.737 10.37,-19.737 ; 10.294,-17.959 11.158,-17.959 ; 10.294,-16.079 11.462,-16.079 ; 10.294,-16.054 11.462,-16.054 ; 10.294,-16.028 11.462,-16.028 ; 10.294,-16.003 11.462,-16.003 ; 10.294,-15.825 11.005,-15.825 ; 10.319,-20.092 11.005,-20.092 ; 10.319,-19.762 10.472,-19.762 ; 10.319,-18.721 11.183,-18.721 ; 10.319,-14.707 10.929,-14.707 ; 10.345,-19.787 10.497,-19.787 ; 10.345,-15.8 11.488,-15.8 ; 10.37,-20.346 10.624,-20.346 ; 10.37,-20.067 10.98,-20.067 ; 10.37,-19.813 10.599,-19.813 ; 10.37,-17.984 11.742,-17.984 ; 10.37,-15.774 11.513,-15.774 ; 10.37,-14.682 10.98,-14.682 ; 10.396,-19.864 10.7,-19.864 ; 10.396,-19.838 10.65,-19.838 ; 10.421,-21.413 11.031,-21.413 ; 10.421,-20.372 10.599,-20.372 ; 10.421,-20.041 10.954,-20.041 ; 10.421,-19.914 10.777,-19.914 ; 10.421,-19.889 10.751,-19.889 ; 10.421,-14.657 11.056,-14.657 ; 10.446,-20.016 10.929,-20.016 ; 10.446,-19.991 10.904,-19.991 ; 10.446,-19.965 10.853,-19.965 ; 10.446,-19.94 10.827,-19.94 ; 10.446,-18.746 11.259,-18.746 ; 10.446,-15.749 11.564,-15.749 ; 10.472,-21.921 10.548,-21.921 ; 10.472,-18.009 11.716,-18.009 ; 10.472,-15.723 11.589,-15.723 ; 10.472,-14.631 11.107,-14.631 ; 10.497,-21.972 10.548,-21.972 ; 10.497,-21.946 10.548,-21.946 ; 10.497,-21.388 11.107,-21.388 ; 10.497,-18.035 11.716,-18.035 ; 10.523,-18.771 11.285,-18.771 ; 10.523,-14.606 11.183,-14.606 ; 10.548,-21.362 11.158,-21.362 ; 10.548,-20.397 10.599,-20.397 ; 10.548,-15.698 11.615,-15.698 ; 10.548,-14.58 11.234,-14.58 ; 10.573,-20.422 10.599,-20.422 ; 10.573,-19.254 12.58,-19.254 ; 10.599,-18.06 11.666,-18.06 ; 10.599,-14.555 11.335,-14.555 ; 10.624,-21.337 11.285,-21.337 ; 10.624,-19.279 12.656,-19.279 ; 10.624,-15.673 11.64,-15.673 ; 10.65,-21.311 11.386,-21.311 ; 10.65,-18.086 11.64,-18.086 ; 10.65,-15.647 11.666,-15.647 ; 10.675,-14.53 11.462,-14.53 ; 10.7,-14.504 11.513,-14.504 ; 10.726,-21.286 12.478,-21.286 ; 10.726,-18.111 11.615,-18.111 ; 10.751,-15.622 11.716,-15.622 ; 10.751,-14.479 11.64,-14.479 ; 10.777,-21.261 12.478,-21.261 ; 10.777,-20.321 11.183,-20.321 ; 10.777,-19.305 12.783,-19.305 ; 10.777,-19.229 12.428,-19.229 ; 10.777,-14.453 11.742,-14.453 ; 10.802,-18.136 11.564,-18.136 ; 10.802,-16.739 10.98,-16.739 ; 10.802,-15.596 11.742,-15.596 ; 10.827,-18.797 11.005,-18.797 ; 10.853,-21.235 12.478,-21.235 ; 10.853,-14.428 12.986,-14.428 ; 10.878,-21.21 12.453,-21.21 ; 10.878,-20.346 11.183,-20.346 ; 10.878,-19.33 12.834,-19.33 ; 10.878,-14.403 13.012,-14.403 ; 10.904,-15.571 11.742,-15.571 ; 10.929,-20.372 11.208,-20.372 ; 10.929,-19.203 12.301,-19.203 ; 10.929,-14.377 13.088,-14.377 ; 10.954,-21.184 12.428,-21.184 ; 10.954,-18.162 11.462,-18.162 ; 10.954,-15.546 11.793,-15.546 ; 10.954,-14.352 13.113,-14.352 ; 10.98,-16.714 11.005,-16.714 ; 11.005,-20.397 11.234,-20.397 ; 11.005,-19.356 12.936,-19.356 ; 11.005,-14.326 13.037,-14.326 ; 11.056,-21.159 12.428,-21.159 ; 11.056,-20.422 11.234,-20.422 ; 11.056,-18.187 11.412,-18.187 ; 11.056,-15.927 11.488,-15.927 ; 11.056,-15.825 11.488,-15.825 ; 11.056,-15.52 11.818,-15.52 ; 11.056,-14.301 12.809,-14.301 ; 11.081,-15.85 11.488,-15.85 ; 11.081,-14.276 12.707,-14.276 ; 11.107,-21.134 12.428,-21.134 ; 11.107,-20.448 11.234,-20.448 ; 11.107,-15.901 11.488,-15.901 ; 11.107,-15.876 11.488,-15.876 ; 11.107,-15.495 11.843,-15.495 ; 11.107,-14.25 12.555,-14.25 ; 11.158,-20.473 11.259,-20.473 ; 11.158,-19.381 13.012,-19.381 ; 11.158,-14.225 12.529,-14.225 ; 11.183,-15.469 11.843,-15.469 ; 11.183,-14.199 12.377,-14.199 ; 11.208,-21.108 12.402,-21.108 ; 11.208,-20.499 11.285,-20.499 ; 11.208,-19.406 13.063,-19.406 ; 11.208,-14.174 12.326,-14.174 ; 11.234,-17.247 13.85,-17.247 ; 11.259,-14.149 12.199,-14.149 ; 11.285,-21.083 12.377,-21.083 ; 11.285,-15.444 11.869,-15.444 ; 11.285,-15.139 11.335,-15.139 ; 11.285,-14.123 12.123,-14.123 ; 11.31,-17.273 13.748,-17.273 ; 11.31,-14.098 11.97,-14.098 ; 11.335,-19.432 13.164,-19.432 ; 11.335,-19.178 11.97,-19.178 ; 11.335,-15.419 11.894,-15.419 ; 11.361,-15.114 11.412,-15.114 ; 11.361,-14.072 12.072,-14.072 ; 11.386,-19.457 13.19,-19.457 ; 11.386,-18.898 11.564,-18.898 ; 11.386,-15.088 11.437,-15.088 ; 11.386,-14.047 12.148,-14.047 ; 11.412,-15.393 11.92,-15.393 ; 11.412,-14.022 12.301,-14.022 ; 11.437,-15.368 12.25,-15.368 ; 11.437,-15.063 11.513,-15.063 ; 11.437,-13.996 12.351,-13.996 ; 11.462,-21.057 11.92,-21.057 ; 11.462,-18.873 11.92,-18.873 ; 11.462,-16.282 11.513,-16.282 ; 11.462,-15.038 11.564,-15.038 ; 11.462,-13.971 12.453,-13.971 ; 11.488,-19.483 13.24,-19.483 ; 11.513,-19.508 13.291,-19.508 ; 11.513,-18.848 13.698,-18.848 ; 11.513,-17.298 13.571,-17.298 ; 11.513,-16.257 11.691,-16.257 ; 11.513,-15.342 12.326,-15.342 ; 11.513,-15.012 11.64,-15.012 ; 11.513,-13.945 12.504,-13.945 ; 11.539,-16.231 11.767,-16.231 ; 11.539,-13.92 14.612,-13.92 ; 11.539,-13.895 14.637,-13.895 ; 11.564,-15.317 12.91,-15.317 ; 11.564,-14.987 11.691,-14.987 ; 11.589,-18.822 13.621,-18.822 ; 11.589,-16.206 11.869,-16.206 ; 11.615,-19.533 13.342,-19.533 ; 11.615,-16.181 11.92,-16.181 ; 11.615,-15.292 12.936,-15.292 ; 11.615,-14.961 11.742,-14.961 ; 11.64,-19.559 13.393,-19.559 ; 11.64,-18.797 13.571,-18.797 ; 11.64,-15.266 12.936,-15.266 ; 11.64,-14.936 11.818,-14.936 ; 11.64,-13.869 14.663,-13.869 ; 11.666,-16.155 12.021,-16.155 ; 11.691,-17.959 11.767,-17.959 ; 11.691,-16.13 12.097,-16.13 ; 11.691,-15.241 12.936,-15.241 ; 11.691,-14.911 11.843,-14.911 ; 11.716,-19.584 13.444,-19.584 ; 11.716,-15.215 12.961,-15.215 ; 11.742,-18.771 13.469,-18.771 ; 11.742,-17.324 13.317,-17.324 ; 11.742,-16.104 12.148,-16.104 ; 11.742,-15.19 12.961,-15.19 ; 11.742,-14.885 11.92,-14.885 ; 11.742,-14.86 11.97,-14.86 ; 11.767,-17.933 11.793,-17.933 ; 11.767,-16.079 12.199,-16.079 ; 11.793,-19.61 12.605,-19.61 ; 11.793,-18.746 13.418,-18.746 ; 11.793,-16.054 12.224,-16.054 ; 11.793,-15.165 12.986,-15.165 ; 11.793,-15.139 12.986,-15.139 ; 11.793,-14.834 12.047,-14.834 ; 11.793,-13.844 14.663,-13.844 ; 11.818,-20.6 11.843,-20.6 ; 11.818,-20.575 11.843,-20.575 ; 11.818,-20.549 11.843,-20.549 ; 11.818,-19.635 12.555,-19.635 ; 11.818,-15.114 13.012,-15.114 ; 11.818,-14.809 12.072,-14.809 ; 11.843,-21.311 12.478,-21.311 ; 11.843,-20.702 11.92,-20.702 ; 11.843,-20.676 11.92,-20.676 ; 11.843,-20.651 11.869,-20.651 ; 11.843,-20.626 11.869,-20.626 ; 11.843,-16.028 12.301,-16.028 ; 11.843,-16.003 12.301,-16.003 ; 11.843,-15.088 13.037,-15.088 ; 11.843,-13.818 14.663,-13.818 ; 11.869,-20.778 11.97,-20.778 ; 11.869,-20.753 11.97,-20.753 ; 11.869,-20.727 11.945,-20.727 ; 11.869,-19.66 12.478,-19.66 ; 11.869,-15.977 12.377,-15.977 ; 11.869,-14.784 12.148,-14.784 ; 11.894,-20.829 12.021,-20.829 ; 11.894,-20.803 12.021,-20.803 ; 11.894,-14.758 12.224,-14.758 ; 11.92,-20.88 12.097,-20.88 ; 11.92,-20.854 12.072,-20.854 ; 11.92,-19.686 12.453,-19.686 ; 11.92,-18.721 13.291,-18.721 ; 11.92,-17.349 13.164,-17.349 ; 11.92,-15.952 12.377,-15.952 ; 11.92,-15.063 13.113,-15.063 ; 11.92,-14.733 12.25,-14.733 ; 11.945,-21.337 12.478,-21.337 ; 11.945,-20.905 12.148,-20.905 ; 11.945,-19.711 12.428,-19.711 ; 11.945,-15.927 12.428,-15.927 ; 11.945,-15.393 12.174,-15.393 ; 11.945,-14.707 12.326,-14.707 ; 11.97,-20.956 12.199,-20.956 ; 11.97,-20.93 12.148,-20.93 ; 11.97,-19.762 12.402,-19.762 ; 11.97,-19.737 12.428,-19.737 ; 11.97,-14.682 12.377,-14.682 ; 11.97,-13.793 13.85,-13.793 ; 11.996,-19.787 12.402,-19.787 ; 11.996,-18.695 13.24,-18.695 ; 11.996,-15.901 12.478,-15.901 ; 12.021,-21.007 12.301,-21.007 ; 12.021,-20.981 12.275,-20.981 ; 12.021,-19.914 12.478,-19.914 ; 12.021,-19.889 12.453,-19.889 ; 12.021,-19.864 12.428,-19.864 ; 12.021,-19.838 12.428,-19.838 ; 12.021,-19.813 12.402,-19.813 ; 12.021,-15.876 12.478,-15.876 ; 12.021,-15.038 13.139,-15.038 ; 12.021,-14.657 12.453,-14.657 ; 12.021,-14.631 12.478,-14.631 ; 12.021,-13.768 13.748,-13.768 ; 12.047,-20.016 12.605,-20.016 ; 12.047,-19.991 12.58,-19.991 ; 12.047,-19.965 12.529,-19.965 ; 12.047,-19.94 12.504,-19.94 ; 12.047,-15.85 12.529,-15.85 ; 12.047,-14.606 12.555,-14.606 ; 12.047,-14.453 12.885,-14.453 ; 12.072,-21.362 12.478,-21.362 ; 12.072,-21.057 12.351,-21.057 ; 12.072,-21.032 12.326,-21.032 ; 12.072,-20.118 12.885,-20.118 ; 12.072,-20.092 12.783,-20.092 ; 12.072,-20.067 12.758,-20.067 ; 12.072,-20.041 12.656,-20.041 ; 12.072,-15.825 12.555,-15.825 ; 12.072,-14.58 12.605,-14.58 ; 12.072,-14.555 12.682,-14.555 ; 12.072,-14.53 12.758,-14.53 ; 12.072,-14.504 12.783,-14.504 ; 12.072,-14.479 12.859,-14.479 ; 12.097,-21.388 12.478,-21.388 ; 12.097,-20.194 13.088,-20.194 ; 12.097,-20.168 13.037,-20.168 ; 12.097,-20.143 12.936,-20.143 ; 12.097,-15.8 12.58,-15.8 ; 12.097,-15.774 12.605,-15.774 ; 12.123,-13.742 13.621,-13.742 ; 12.148,-20.245 13.317,-20.245 ; 12.148,-20.219 13.24,-20.219 ; 12.148,-18.67 13.088,-18.67 ; 12.148,-17.222 14.002,-17.222 ; 12.148,-15.749 12.631,-15.749 ; 12.148,-15.723 12.656,-15.723 ; 12.174,-15.698 12.682,-15.698 ; 12.199,-21.413 12.326,-21.413 ; 12.199,-20.27 13.444,-20.27 ; 12.199,-15.673 12.707,-15.673 ; 12.199,-15.647 12.707,-15.647 ; 12.199,-13.717 13.571,-13.717 ; 12.25,-21.438 12.275,-21.438 ; 12.25,-16.206 13.647,-16.206 ; 12.25,-15.622 12.758,-15.622 ; 12.25,-15.596 12.758,-15.596 ; 12.25,-15.012 13.19,-15.012 ; 12.275,-20.295 13.215,-20.295 ; 12.275,-16.181 13.647,-16.181 ; 12.275,-15.571 12.783,-15.571 ; 12.275,-15.546 12.783,-15.546 ; 12.301,-15.52 12.783,-15.52 ; 12.301,-15.495 12.809,-15.495 ; 12.301,-13.691 13.698,-13.691 ; 12.326,-20.321 13.088,-20.321 ; 12.326,-17.197 14.079,-17.197 ; 12.326,-16.155 13.672,-16.155 ; 12.326,-15.469 12.834,-15.469 ; 12.326,-15.444 12.834,-15.444 ; 12.326,-15.419 12.859,-15.419 ; 12.351,-15.393 12.885,-15.393 ; 12.351,-13.666 13.748,-13.666 ; 12.377,-18.873 13.723,-18.873 ; 12.377,-15.368 12.885,-15.368 ; 12.377,-15.342 12.91,-15.342 ; 12.428,-18.644 12.834,-18.644 ; 12.428,-16.13 13.698,-16.13 ; 12.453,-16.104 13.723,-16.104 ; 12.478,-13.641 13.901,-13.641 ; 12.504,-16.231 13.621,-16.231 ; 12.504,-14.987 13.24,-14.987 ; 12.529,-16.079 13.748,-16.079 ; 12.555,-17.171 14.206,-17.171 ; 12.555,-16.054 13.799,-16.054 ; 12.555,-13.971 13.444,-13.971 ; 12.555,-13.945 14.587,-13.945 ; 12.58,-13.615 13.977,-13.615 ; 12.605,-16.257 13.621,-16.257 ; 12.605,-14.961 13.24,-14.961 ; 12.631,-17.146 14.282,-17.146 ; 12.631,-13.59 14.053,-13.59 ; 12.656,-16.028 13.85,-16.028 ; 12.707,-18.898 13.799,-18.898 ; 12.707,-16.003 13.85,-16.003 ; 12.707,-14.758 12.783,-14.758 ; 12.732,-13.564 14.155,-13.564 ; 12.758,-14.733 12.859,-14.733 ; 12.783,-17.12 14.383,-17.12 ; 12.783,-16.282 13.621,-16.282 ; 12.783,-15.977 13.926,-15.977 ; 12.783,-13.539 14.206,-13.539 ; 12.834,-16.308 13.621,-16.308 ; 12.834,-15.952 13.952,-15.952 ; 12.834,-14.936 13.291,-14.936 ; 12.859,-18.924 13.875,-18.924 ; 12.859,-17.095 14.46,-17.095 ; 12.859,-14.707 13.012,-14.707 ; 12.91,-14.682 13.063,-14.682 ; 12.91,-13.514 14.282,-13.514 ; 12.936,-18.949 13.901,-18.949 ; 12.936,-15.927 14.028,-15.927 ; 12.936,-14.911 13.317,-14.911 ; 12.961,-13.488 14.333,-13.488 ; 12.986,-17.07 14.561,-17.07 ; 12.986,-16.333 13.621,-16.333 ; 12.986,-14.657 13.215,-14.657 ; 13.012,-15.901 14.104,-15.901 ; 13.012,-14.631 13.266,-14.631 ; 13.037,-19.61 13.494,-19.61 ; 13.037,-16.358 13.621,-16.358 ; 13.063,-18.975 13.952,-18.975 ; 13.063,-17.044 14.587,-17.044 ; 13.063,-13.463 14.409,-13.463 ; 13.088,-15.876 14.155,-15.876 ; 13.088,-14.885 13.367,-14.885 ; 13.088,-14.606 13.393,-14.606 ; 13.113,-19 13.977,-19 ; 13.113,-17.019 14.536,-17.019 ; 13.113,-14.58 13.469,-14.58 ; 13.113,-13.437 14.46,-13.437 ; 13.139,-19.635 13.52,-19.635 ; 13.139,-16.384 13.621,-16.384 ; 13.164,-14.86 13.393,-14.86 ; 13.19,-15.85 14.231,-15.85 ; 13.19,-14.555 13.571,-14.555 ; 13.215,-19.025 14.053,-19.025 ; 13.215,-16.993 14.434,-16.993 ; 13.215,-16.409 13.621,-16.409 ; 13.215,-13.412 14.536,-13.412 ; 13.24,-16.968 14.409,-16.968 ; 13.24,-15.825 14.282,-15.825 ; 13.24,-14.53 13.672,-14.53 ; 13.266,-19.051 14.079,-19.051 ; 13.266,-16.435 13.621,-16.435 ; 13.291,-19.66 13.571,-19.66 ; 13.291,-16.943 14.333,-16.943 ; 13.291,-14.834 13.418,-14.834 ; 13.291,-14.504 13.698,-14.504 ; 13.317,-15.063 13.342,-15.063 ; 13.317,-13.387 14.587,-13.387 ; 13.342,-19.686 13.596,-19.686 ; 13.342,-16.917 14.307,-16.917 ; 13.342,-16.485 13.672,-16.485 ; 13.342,-16.46 13.647,-16.46 ; 13.342,-15.038 13.393,-15.038 ; 13.342,-14.809 13.444,-14.809 ; 13.342,-14.479 13.799,-14.479 ; 13.367,-19.076 14.129,-19.076 ; 13.367,-15.8 14.383,-15.8 ; 13.367,-14.453 13.85,-14.453 ; 13.367,-13.361 14.637,-13.361 ; 13.393,-19.102 14.155,-19.102 ; 13.393,-16.892 14.231,-16.892 ; 13.393,-16.866 14.206,-16.866 ; 13.393,-16.511 13.672,-16.511 ; 13.393,-15.012 13.469,-15.012 ; 13.418,-14.428 13.926,-14.428 ; 13.444,-19.711 13.647,-19.711 ; 13.444,-16.841 14.129,-16.841 ; 13.444,-16.536 13.698,-16.536 ; 13.444,-15.774 14.434,-15.774 ; 13.444,-14.987 13.52,-14.987 ; 13.444,-14.784 13.469,-14.784 ; 13.444,-14.403 13.952,-14.403 ; 13.469,-19.127 14.206,-19.127 ; 13.469,-16.816 14.079,-16.816 ; 13.469,-16.79 14.028,-16.79 ; 13.469,-16.587 13.748,-16.587 ; 13.469,-16.562 13.698,-16.562 ; 13.469,-14.961 13.571,-14.961 ; 13.469,-14.377 14.028,-14.377 ; 13.469,-13.336 14.993,-13.336 ; 13.494,-19.737 13.672,-19.737 ; 13.494,-16.765 13.977,-16.765 ; 13.494,-16.739 13.952,-16.739 ; 13.494,-16.612 13.748,-16.612 ; 13.52,-16.714 13.901,-16.714 ; 13.52,-16.689 13.901,-16.689 ; 13.52,-16.663 13.825,-16.663 ; 13.52,-16.638 13.799,-16.638 ; 13.52,-14.936 13.647,-14.936 ; 13.52,-14.352 14.079,-14.352 ; 13.52,-13.31 14.968,-13.31 ; 13.545,-19.152 14.256,-19.152 ; 13.545,-14.911 13.698,-14.911 ; 13.545,-14.326 14.129,-14.326 ; 13.571,-19.178 14.307,-19.178 ; 13.571,-15.749 14.536,-15.749 ; 13.596,-19.762 13.698,-19.762 ; 13.596,-14.301 14.18,-14.301 ; 13.621,-19.787 13.723,-19.787 ; 13.621,-15.723 14.587,-15.723 ; 13.621,-14.885 13.774,-14.885 ; 13.621,-14.86 13.799,-14.86 ; 13.621,-14.276 14.206,-14.276 ; 13.621,-13.285 14.942,-13.285 ; 13.672,-19.229 14.383,-19.229 ; 13.672,-19.203 14.358,-19.203 ; 13.672,-14.25 14.256,-14.25 ; 13.672,-14.225 14.282,-14.225 ; 13.672,-13.26 14.942,-13.26 ; 13.698,-19.813 13.774,-19.813 ; 13.698,-14.834 13.901,-14.834 ; 13.698,-14.809 13.952,-14.809 ; 13.698,-14.199 14.333,-14.199 ; 13.723,-14.174 14.358,-14.174 ; 13.723,-13.971 14.587,-13.971 ; 13.748,-19.254 14.434,-19.254 ; 13.748,-14.149 14.383,-14.149 ; 13.748,-13.234 14.917,-13.234 ; 13.774,-19.838 13.799,-19.838 ; 13.774,-19.279 14.434,-19.279 ; 13.774,-14.784 14.053,-14.784 ; 13.774,-14.123 14.409,-14.123 ; 13.799,-19.864 13.825,-19.864 ; 13.799,-15.698 14.714,-15.698 ; 13.799,-14.098 14.46,-14.098 ; 13.799,-13.209 14.917,-13.209 ; 13.825,-14.758 14.155,-14.758 ; 13.85,-19.33 14.536,-19.33 ; 13.85,-19.305 14.485,-19.305 ; 13.85,-14.733 14.206,-14.733 ; 13.85,-14.072 14.485,-14.072 ; 13.85,-14.047 14.51,-14.047 ; 13.875,-14.022 14.536,-14.022 ; 13.901,-14.707 14.333,-14.707 ; 13.901,-13.996 14.561,-13.996 ; 13.901,-13.183 14.891,-13.183 ; 13.926,-19.356 14.587,-19.356 ; 13.926,-14.682 14.383,-14.682 ; 13.977,-19.381 14.612,-19.381 ; 13.977,-15.673 14.841,-15.673 ; 13.977,-14.657 14.536,-14.657 ; 14.002,-19.406 14.637,-19.406 ; 14.002,-13.158 14.891,-13.158 ; 14.028,-14.631 14.587,-14.631 ; 14.053,-13.133 14.891,-13.133 ; 14.079,-19.457 14.714,-19.457 ; 14.079,-19.432 14.688,-19.432 ; 14.079,-14.606 14.739,-14.606 ; 14.104,-15.647 14.917,-15.647 ; 14.104,-14.58 14.815,-14.58 ; 14.129,-13.107 14.866,-13.107 ; 14.155,-19.483 14.764,-19.483 ; 14.155,-14.555 14.993,-14.555 ; 14.18,-19.508 14.79,-19.508 ; 14.18,-13.082 14.866,-13.082 ; 14.206,-14.53 15.12,-14.53 ; 14.231,-19.533 14.841,-19.533 ; 14.256,-14.504 15.222,-14.504 ; 14.256,-13.056 14.866,-13.056 ; 14.282,-19.559 14.866,-19.559 ; 14.307,-14.479 15.349,-14.479 ; 14.307,-13.031 14.866,-13.031 ; 14.333,-19.584 14.917,-19.584 ; 14.333,-14.453 15.425,-14.453 ; 14.383,-14.428 15.526,-14.428 ; 14.409,-19.61 14.968,-19.61 ; 14.409,-15.622 15.069,-15.622 ; 14.409,-13.006 14.866,-13.006 ; 14.434,-19.635 14.993,-19.635 ; 14.434,-14.403 15.526,-14.403 ; 14.46,-12.98 14.866,-12.98 ; 14.485,-14.377 15.501,-14.377 ; 14.51,-14.352 15.501,-14.352 ; 14.536,-19.66 15.018,-19.66 ; 14.536,-12.955 14.866,-12.955 ; 14.561,-14.326 15.476,-14.326 ; 14.612,-19.686 14.942,-19.686 ; 14.612,-14.301 15.45,-14.301 ; 14.612,-12.929 14.866,-12.929 ; 14.637,-14.276 15.45,-14.276 ; 14.663,-15.596 15.12,-15.596 ; 14.663,-12.904 14.866,-12.904 ; 14.688,-14.25 15.45,-14.25 ; 14.714,-14.225 15.45,-14.225 ; 14.764,-14.199 15.425,-14.199 ; 14.764,-13.387 15.044,-13.387 ; 14.764,-13.361 15.044,-13.361 ; 14.764,-12.879 14.866,-12.879 ; 14.79,-14.174 15.399,-14.174 ; 14.79,-12.853 14.891,-12.853 ; 14.815,-14.149 15.399,-14.149 ; 14.815,-13.437 15.145,-13.437 ; 14.815,-13.412 15.095,-13.412 ; 14.841,-14.123 15.399,-14.123 ; 14.841,-13.463 15.171,-13.463 ; 14.866,-13.514 15.272,-13.514 ; 14.866,-13.488 15.222,-13.488 ; 14.891,-14.098 15.399,-14.098 ; 14.891,-13.539 15.349,-13.539 ; 14.917,-14.072 15.374,-14.072 ; 14.917,-13.564 15.349,-13.564 ; 14.942,-14.047 15.374,-14.047 ; 14.942,-14.022 15.374,-14.022 ; 14.942,-13.615 15.349,-13.615 ; 14.942,-13.59 15.349,-13.59 ; 14.968,-13.996 15.349,-13.996 ; 14.968,-13.641 15.349,-13.641 ; 14.993,-13.971 15.349,-13.971 ; 14.993,-13.945 15.349,-13.945 ; 14.993,-13.742 15.349,-13.742 ; 14.993,-13.717 15.349,-13.717 ; 14.993,-13.691 15.349,-13.691 ; 14.993,-13.666 15.349,-13.666 ; 15.018,-13.92 15.349,-13.92 ; 15.018,-13.895 15.349,-13.895 ; 15.018,-13.869 15.349,-13.869 ; 15.018,-13.844 15.349,-13.844 ; 15.018,-13.818 15.349,-13.818 ; 15.018,-13.793 15.349,-13.793 ; 15.018,-13.768 15.349,-13.768

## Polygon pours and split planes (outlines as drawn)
GND on Top Layer "Mechanical 1-No Net" (solid, pour order 1000): 11.2,-23.575 14.45,-20.325 14.925,-20.325 15.475,-19.775 15.475,-16.125 16.5,-15.1 16.5,-12.425 15.2,-11.125 12.525,-11.125 6.525,-17.125 6.525,-21.65 8.45,-23.575 11.2,-23.575 11.2,-24.45 45.85,-24.45 45.85,0 0,0 0,-24.45 11.2,-24.45 11.2,-23.575

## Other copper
Top Layer:
  text "IR-USB" at 34.825,-3.6 h1.52
  text "Girder" at 33.75,-23.525 h1.52

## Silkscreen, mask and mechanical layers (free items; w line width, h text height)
Mechanical 1:
  lines w0.254: 0,-24.45 45.85,-24.45 45.85,0 0,0 0,-24.45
